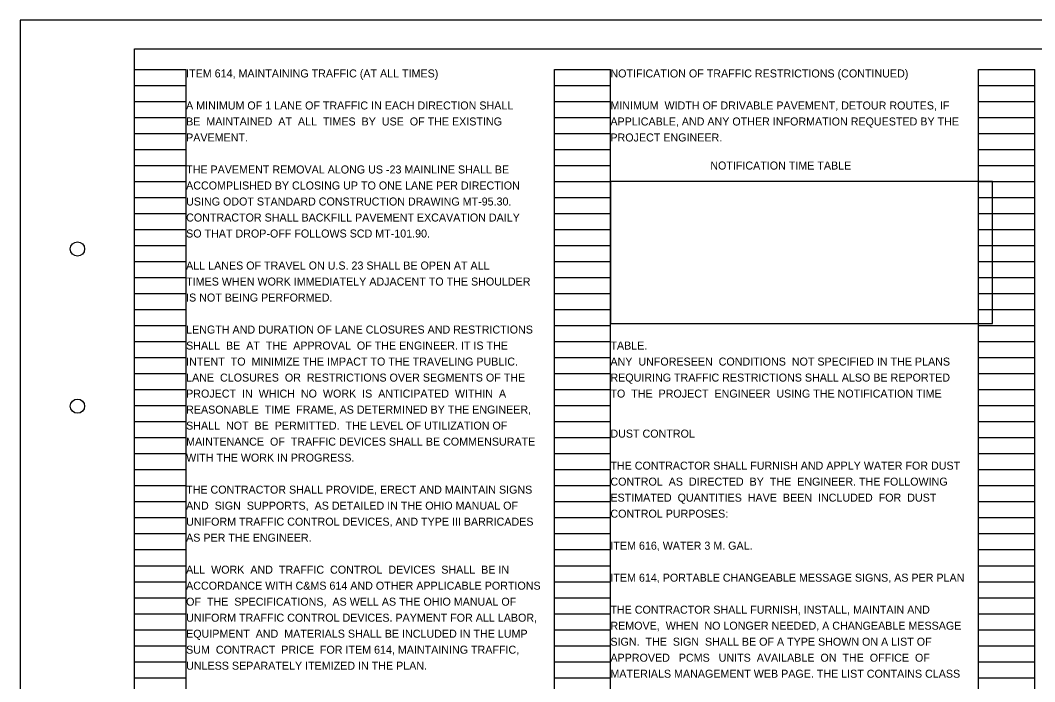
# Model space of a CAD drawing. Extents: x -51 to 34, y 0 to 22.
# Drawn here: x 0 to 17.74, y 10.43 to 22 of the extents above; entities that cross this region are included whole.
import ezdxf

# ---------------------------------------------------------------- set-up
doc = ezdxf.new("R2010")
doc.units = 0
for name, color, linetype in [('SH_Border', 7, 'Continuous'), ('SH_Cut_Line', 7, 'Continuous'), ('SH_Data', 7, 'Continuous'), ('SH_Text', 7, 'Continuous'), ('TX_P_5', 7, 'Continuous')]:
    doc.layers.add(name, color=color, linetype=linetype)

msp = doc.modelspace()

# ---------------------------------------------------------------- linework, layer by layer
at = {"layer": 'SH_Border'}
msp.add_lwpolyline([(2, 21.5), (33.5, 21.5), (33.5, 0.5), (2, 0.5)], close=True, dxfattribs=at)
for centre in [(1, 18), (1, 15.25)]:
    msp.add_circle(centre, 0.125, dxfattribs=at)
at = {"layer": 'SH_Cut_Line'}
msp.add_lwpolyline([(0, 0), (34, 0), (34, 22), (0, 22)], close=True, dxfattribs=at)
at = {"layer": 'SH_Data'}
for p, q in [((2, 0.98), (2, 21.14)), ((2, 21.14), (2.9, 21.14)), ((2.9, 0.98), (2.9, 21.14)), ((9.34, 0.98), (9.34, 21.14)), ((9.34, 21.14), (10.32, 21.14)), ((10.32, 0.98), (10.32, 21.14)), ((16.76, 0.98), (16.76, 21.14)), ((16.76, 21.14), (17.74, 21.14)), ((17.74, 0.98), (17.74, 21.14)), ((2, 20.86), (2.9, 20.86)), ((9.34, 20.86), (10.32, 20.86)), ((16.76, 20.86), (17.74, 20.86)), ((2, 20.58), (2.9, 20.58)), ((9.34, 20.58), (10.32, 20.58)), ((16.76, 20.58), (17.74, 20.58)), ((2, 20.3), (2.9, 20.3)), ((9.34, 20.3), (10.32, 20.3)), ((16.76, 20.3), (17.74, 20.3)), ((2, 20.02), (2.9, 20.02)), ((9.34, 20.02), (10.32, 20.02)), ((16.76, 20.02), (17.74, 20.02)), ((2, 19.74), (2.9, 19.74)), ((9.34, 19.74), (10.32, 19.74)), ((16.76, 19.74), (17.74, 19.74)), ((2, 19.46), (2.9, 19.46)), ((9.34, 19.46), (10.32, 19.46)), ((16.76, 19.46), (17.74, 19.46)), ((2, 19.18), (2.9, 19.18)), ((9.34, 19.18), (10.32, 19.18)), ((16.76, 19.18), (17.74, 19.18)), ((2, 18.9), (2.9, 18.9)), ((9.34, 18.9), (10.32, 18.9)), ((16.76, 18.9), (17.74, 18.9)), ((2, 18.62), (2.9, 18.62)), ((9.34, 18.62), (10.32, 18.62)), ((16.76, 18.62), (17.74, 18.62)), ((2, 18.34), (2.9, 18.34)), ((9.34, 18.34), (10.32, 18.34)), ((16.76, 18.34), (17.74, 18.34)), ((2, 18.06), (2.9, 18.06)), ((9.34, 18.06), (10.32, 18.06)), ((16.76, 18.06), (17.74, 18.06)), ((2, 17.78), (2.9, 17.78)), ((9.34, 17.78), (10.32, 17.78)), ((16.76, 17.78), (17.74, 17.78)), ((2, 17.5), (2.9, 17.5)), ((9.34, 17.5), (10.32, 17.5)), ((16.76, 17.5), (17.74, 17.5)), ((2, 17.22), (2.9, 17.22)), ((9.34, 17.22), (10.32, 17.22)), ((16.76, 17.22), (17.74, 17.22)), ((2, 16.94), (2.9, 16.94)), ((9.34, 16.94), (10.32, 16.94)), ((16.76, 16.94), (17.74, 16.94)), ((2, 16.66), (2.9, 16.66)), ((9.34, 16.66), (10.32, 16.66)), ((16.76, 16.66), (17.74, 16.66)), ((2, 16.38), (2.9, 16.38)), ((9.34, 16.38), (10.32, 16.38)), ((16.76, 16.38), (17.74, 16.38)), ((2, 16.1), (2.9, 16.1)), ((9.34, 16.1), (10.32, 16.1)), ((16.76, 16.1), (17.74, 16.1)), ((2, 15.82), (2.9, 15.82)), ((9.34, 15.82), (10.32, 15.82)), ((16.76, 15.82), (17.74, 15.82)), ((2, 15.54), (2.9, 15.54)), ((9.34, 15.54), (10.32, 15.54)), ((16.76, 15.54), (17.74, 15.54)), ((2, 15.26), (2.9, 15.26)), ((9.34, 15.26), (10.32, 15.26)), ((16.76, 15.26), (17.74, 15.26)), ((2, 14.98), (2.9, 14.98)), ((9.34, 14.98), (10.32, 14.98)), ((16.76, 14.98), (17.74, 14.98)), ((2, 14.7), (2.9, 14.7)), ((9.34, 14.7), (10.32, 14.7)), ((16.76, 14.7), (17.74, 14.7)), ((2, 14.42), (2.9, 14.42)), ((9.34, 14.42), (10.32, 14.42)), ((16.76, 14.42), (17.74, 14.42)), ((2, 14.14), (2.9, 14.14)), ((9.34, 14.14), (10.32, 14.14)), ((16.76, 14.14), (17.74, 14.14)), ((2, 13.86), (2.9, 13.86)), ((9.34, 13.86), (10.32, 13.86)), ((16.76, 13.86), (17.74, 13.86)), ((2, 13.58), (2.9, 13.58)), ((9.34, 13.58), (10.32, 13.58)), ((16.76, 13.58), (17.74, 13.58)), ((2, 13.3), (2.9, 13.3)), ((9.34, 13.3), (10.32, 13.3)), ((16.76, 13.3), (17.74, 13.3)), ((2, 13.02), (2.9, 13.02)), ((9.34, 13.02), (10.32, 13.02)), ((16.76, 13.02), (17.74, 13.02)), ((2, 12.74), (2.9, 12.74)), ((9.34, 12.74), (10.32, 12.74)), ((16.76, 12.74), (17.74, 12.74)), ((2, 12.46), (2.9, 12.46)), ((9.34, 12.46), (10.32, 12.46)), ((16.76, 12.46), (17.74, 12.46)), ((2, 12.18), (2.9, 12.18)), ((9.34, 12.18), (10.32, 12.18)), ((16.76, 12.18), (17.74, 12.18)), ((2, 11.9), (2.9, 11.9)), ((9.34, 11.9), (10.32, 11.9)), ((16.76, 11.9), (17.74, 11.9)), ((2, 11.62), (2.9, 11.62)), ((9.34, 11.62), (10.32, 11.62)), ((16.76, 11.62), (17.74, 11.62)), ((2, 11.34), (2.9, 11.34)), ((9.34, 11.34), (10.32, 11.34)), ((16.76, 11.34), (17.74, 11.34)), ((2, 11.06), (2.9, 11.06)), ((9.34, 11.06), (10.32, 11.06)), ((16.76, 11.06), (17.74, 11.06)), ((2, 10.78), (2.9, 10.78)), ((9.34, 10.78), (10.32, 10.78)), ((16.76, 10.78), (17.74, 10.78)), ((2, 10.5), (2.9, 10.5)), ((9.34, 10.5), (10.32, 10.5)), ((16.76, 10.5), (17.74, 10.5))]:
    msp.add_line(p, q, dxfattribs=at)
at = {"layer": 'TX_P_5'}
msp.add_lwpolyline([(10.32, 16.697), (17, 16.697), (17, 19.18), (10.32, 19.18)], close=True, dxfattribs=at)

# ---------------------------------------------------------------- texts
at = {"layer": 'SH_Text'}
for s, p in [('ITEM 614, MAINTAINING TRAFFIC (AT ALL TIMES)', (2.9, 21)), ('NOTIFICATION OF TRAFFIC RESTRICTIONS (CONTINUED)', (10.32, 21)), ('A MINIMUM OF 1 LANE OF TRAFFIC IN EACH DIRECTION SHALL', (2.9, 20.44)), ('MINIMUM  WIDTH OF DRIVABLE PAVEMENT, DETOUR ROUTES, IF', (10.32, 20.44)), ('BE  MAINTAINED  AT  ALL  TIMES  BY  USE  OF THE EXISTING', (2.9, 20.16)), ('APPLICABLE, AND ANY OTHER INFORMATION REQUESTED BY THE', (10.32, 20.16)), ('PAVEMENT.', (2.9, 19.88)), ('PROJECT ENGINEER.', (10.32, 19.88)), ('THE PAVEMENT REMOVAL ALONG US -23 MAINLINE SHALL BE', (2.9, 19.32)), ('ACCOMPLISHED BY CLOSING UP TO ONE LANE PER DIRECTION', (2.9, 19.04)), ('USING ODOT STANDARD CONSTRUCTION DRAWING MT-95.30.', (2.9, 18.76)), ('CONTRACTOR SHALL BACKFILL PAVEMENT EXCAVATION DAILY ', (2.9, 18.48)), ('SO THAT DROP-OFF FOLLOWS SCD MT-101.90.', (2.9, 18.2)), ('ALL LANES OF TRAVEL ON U.S. 23 SHALL BE OPEN AT ALL ', (2.9, 17.64)), ('TIMES WHEN WORK IMMEDIATELY ADJACENT TO THE SHOULDER', (2.9, 17.36)), ('IS NOT BEING PERFORMED.', (2.9, 17.08)), ('LENGTH AND DURATION OF LANE CLOSURES AND RESTRICTIONS', (2.9, 16.52)), ('SHALL  BE  AT  THE  APPROVAL  OF THE ENGINEER. IT IS THE', (2.9, 16.24)), ('TABLE.', (10.32, 16.24)), ('INTENT  TO  MINIMIZE THE IMPACT TO THE TRAVELING PUBLIC.', (2.9, 15.96)), ('ANY  UNFORESEEN  CONDITIONS  NOT SPECIFIED IN THE PLANS', (10.32, 15.96)), ('LANE  CLOSURES  OR  RESTRICTIONS OVER SEGMENTS OF THE', (2.9, 15.68)), ('REQUIRING TRAFFIC RESTRICTIONS SHALL ALSO BE REPORTED', (10.32, 15.68)), ('PROJECT  IN  WHICH  NO  WORK  IS  ANTICIPATED  WITHIN  A', (2.9, 15.4)), ('TO  THE  PROJECT  ENGINEER  USING THE NOTIFICATION TIME', (10.32, 15.4)), ('REASONABLE  TIME  FRAME, AS DETERMINED BY THE ENGINEER,', (2.9, 15.12)), ('SHALL  NOT  BE  PERMITTED.  THE LEVEL OF UTILIZATION OF', (2.9, 14.84)), ('DUST CONTROL', (10.32, 14.7)), ('MAINTENANCE  OF  TRAFFIC DEVICES SHALL BE COMMENSURATE', (2.9, 14.56)), ('WITH THE WORK IN PROGRESS.', (2.9, 14.28)), ('THE CONTRACTOR SHALL FURNISH AND APPLY WATER FOR DUST', (10.32, 14.14)), ('THE CONTRACTOR SHALL PROVIDE, ERECT AND MAINTAIN SIGNS', (2.9, 13.72)), ('CONTROL  AS  DIRECTED  BY  THE  ENGINEER. THE FOLLOWING', (10.32, 13.86)), ('ESTIMATED  QUANTITIES  HAVE  BEEN  INCLUDED  FOR  DUST', (10.32, 13.58)), ('AND  SIGN  SUPPORTS,  AS DETAILED IN THE OHIO MANUAL OF', (2.9, 13.44)), ('CONTROL PURPOSES:', (10.32, 13.3)), ('UNIFORM TRAFFIC CONTROL DEVICES, AND TYPE III BARRICADES', (2.9, 13.16)), ('AS PER THE ENGINEER.', (2.9, 12.88)), ('ITEM 616, WATER 3 M. GAL.', (10.32, 12.74)), ('ALL  WORK  AND  TRAFFIC  CONTROL  DEVICES  SHALL  BE IN', (2.9, 12.32)), ('ITEM 614, PORTABLE CHANGEABLE MESSAGE SIGNS, AS PER PLAN', (10.32, 12.18)), ('ACCORDANCE WITH C&MS 614 AND OTHER APPLICABLE PORTIONS', (2.9, 12.04)), ('OF  THE  SPECIFICATIONS,  AS WELL AS THE OHIO MANUAL OF', (2.9, 11.76)), ('THE CONTRACTOR SHALL FURNISH, INSTALL, MAINTAIN AND', (10.32, 11.62)), ('UNIFORM TRAFFIC CONTROL DEVICES. PAYMENT FOR ALL LABOR,', (2.9, 11.48)), ('REMOVE,  WHEN  NO LONGER NEEDED, A CHANGEABLE MESSAGE', (10.32, 11.34)), ('EQUIPMENT  AND  MATERIALS SHALL BE INCLUDED IN THE LUMP', (2.9, 11.2)), ('SIGN.  THE  SIGN  SHALL BE OF A TYPE SHOWN ON A LIST OF', (10.32, 11.06)), ('SUM  CONTRACT  PRICE  FOR ITEM 614, MAINTAINING TRAFFIC,', (2.9, 10.92)), ('APPROVED   PCMS   UNITS  AVAILABLE  ON  THE  OFFICE  OF', (10.32, 10.78)), ('UNLESS SEPARATELY ITEMIZED IN THE PLAN.', (2.9, 10.64)), ('MATERIALS MANAGEMENT WEB PAGE. THE LIST CONTAINS CLASS', (10.32, 10.5))]:
    msp.add_text(s, height=0.14, dxfattribs=at).set_placement(p)
at = {"layer": 'TX_P_5'}
msp.add_text('NOTIFICATION TIME TABLE', height=0.14, dxfattribs=at).set_placement((12.067, 19.389))

doc.saveas('drawing.dxf')
